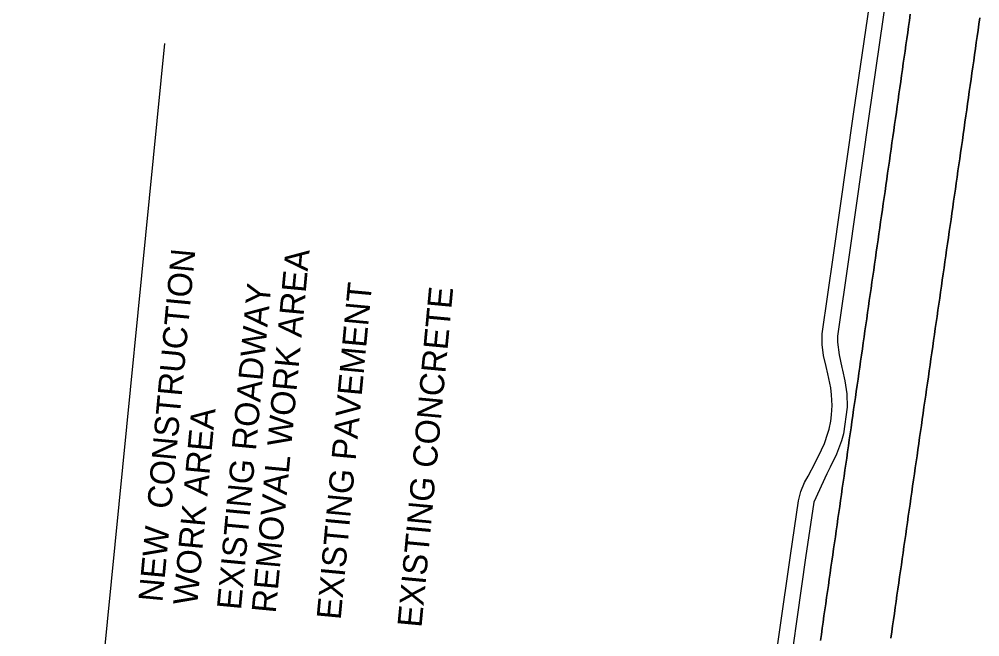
# Model space of a CAD drawing. Extents: x 1795987 to 1799700, y 243690 to 251545.
# Drawn here: x 1797261.4 to 1797570.9, y 247453.1 to 247652.1 of the extents above; entities that cross this region are included whole.
import ezdxf

# ---------------------------------------------------------------- set-up
doc = ezdxf.new("R2010")
doc.units = 0
for name, color, linetype in [('EP', 7, 'Continuous'), ('Level 31', 7, 'Continuous'), ('Prop_Horiz Alignment', 7, 'Continuous')]:
    doc.layers.add(name, color=color, linetype=linetype)

msp = doc.modelspace()

# ---------------------------------------------------------------- linework, layer by layer
at = {"layer": 'EP'}
for points in [[(1797502.98, 247431.42), (1797509.89, 247479.28), (1797512.41, 247496.92), (1797513.21, 247499.92), (1797514.39, 247502.79), (1797515.55, 247504.9), (1797517.77, 247509.13), (1797519.86, 247513.31), (1797520.78, 247515.42), (1797521.93, 247518.67), (1797522.28, 247519.96), (1797522.83, 247522.6), (1797523.1, 247524.61), (1797523.26, 247527.63), (1797523.1, 247531.02), (1797522.82, 247533.27), (1797521.91, 247537.81), (1797521.35, 247540.15), (1797520.54, 247543.7), (1797520.12, 247547.31), (1797520.09, 247550.71), (1797523.74, 247576.05), (1797530.2, 247621.54), (1797536.99, 247668.47)], [(1797541.84, 247667.67), (1797535.11, 247620.83), (1797528.62, 247575.39), (1797524.96, 247549.93), (1797525.06, 247548.02), (1797525.55, 247543.91), (1797526.45, 247539.86), (1797526.65, 247538.96), (1797527.41, 247535.59), (1797527.98, 247531.38), (1797528.16, 247527.13), (1797526.97, 247518.48), (1797526.28, 247516.25), (1797524.64, 247511.95), (1797522.63, 247507.8), (1797522.17, 247506.93), (1797521.53, 247505.59), (1797517.43, 247496.48), (1797514.72, 247478.52), (1797507.92, 247430.67)]]:
    msp.add_lwpolyline(points, dxfattribs=at)
at = {"layer": 'Level 31'}
msp.add_line((1797261.35, 247170.53), (1797308.29, 247644.28), dxfattribs=at)
at = {"layer": 'Prop_Horiz Alignment'}
for points in [[(1797519.54, 247451.89), (1797519.82, 247453.87), (1797520.1, 247455.84), (1797520.38, 247457.81), (1797520.66, 247459.79), (1797520.94, 247461.76), (1797521.23, 247463.73), (1797521.51, 247465.7), (1797521.79, 247467.68), (1797522.07, 247469.65), (1797522.35, 247471.62), (1797522.63, 247473.59), (1797522.91, 247475.55), (1797523.2, 247477.5), (1797523.48, 247479.45), (1797523.76, 247481.4), (1797524.04, 247483.36), (1797524.32, 247485.31), (1797524.6, 247487.26), (1797524.88, 247489.21), (1797525.16, 247491.17), (1797525.44, 247493.12), (1797525.72, 247495.07), (1797526, 247497.02), (1797526.28, 247498.98), (1797526.56, 247500.93), (1797526.85, 247502.88), (1797527.13, 247504.83), (1797527.41, 247506.79), (1797527.69, 247508.74), (1797527.97, 247510.69), (1797528.25, 247512.64), (1797528.53, 247514.6), (1797528.81, 247516.55), (1797529.09, 247518.5), (1797529.37, 247520.45), (1797529.65, 247522.41), (1797529.93, 247524.36), (1797530.21, 247526.31), (1797530.49, 247528.26), (1797530.78, 247530.22), (1797531.06, 247532.17), (1797531.34, 247534.12), (1797531.62, 247536.07), (1797531.9, 247538.03), (1797532.18, 247539.98), (1797532.46, 247541.93), (1797532.74, 247543.88), (1797533.02, 247545.84), (1797533.3, 247547.79), (1797533.58, 247549.74), (1797533.86, 247551.7), (1797534.14, 247553.65), (1797534.42, 247555.6), (1797534.71, 247557.55), (1797534.99, 247559.51), (1797535.27, 247561.46), (1797535.55, 247563.41), (1797535.83, 247565.36), (1797536.11, 247567.32), (1797536.39, 247569.27), (1797536.67, 247571.22), (1797536.95, 247573.17), (1797537.23, 247575.13), (1797537.51, 247577.08), (1797537.79, 247579.03), (1797538.07, 247580.98), (1797538.35, 247582.94), (1797538.64, 247584.89), (1797538.92, 247586.84), (1797539.2, 247588.79), (1797539.48, 247590.75), (1797539.76, 247592.7), (1797540.04, 247594.65), (1797540.32, 247596.6), (1797540.6, 247598.56), (1797540.88, 247600.51), (1797541.16, 247602.46), (1797541.44, 247604.41), (1797541.72, 247606.37), (1797542, 247608.32), (1797542.29, 247610.27), (1797542.57, 247612.24), (1797542.85, 247614.22), (1797543.13, 247616.19), (1797543.41, 247618.17), (1797543.69, 247620.14), (1797543.97, 247622.11), (1797544.25, 247624.09), (1797544.53, 247626.06), (1797544.81, 247628.04), (1797545.1, 247630.01), (1797545.38, 247631.98), (1797545.66, 247633.96), (1797545.94, 247635.93), (1797546.22, 247637.9), (1797546.5, 247639.88), (1797546.78, 247641.85), (1797547.06, 247643.83), (1797547.34, 247645.8), (1797547.63, 247647.77), (1797547.91, 247649.75), (1797548.19, 247651.72), (1797548.47, 247653.7)], [(1797548.47, 247653.7), (1797548.19, 247651.72), (1797547.91, 247649.75), (1797547.63, 247647.77), (1797547.34, 247645.8), (1797547.06, 247643.83), (1797546.78, 247641.85), (1797546.5, 247639.88), (1797546.22, 247637.9), (1797545.94, 247635.93), (1797545.66, 247633.96), (1797545.38, 247631.98), (1797545.1, 247630.01), (1797544.81, 247628.04), (1797544.53, 247626.06), (1797544.25, 247624.09), (1797543.97, 247622.11), (1797543.69, 247620.14), (1797543.41, 247618.17), (1797543.13, 247616.19), (1797542.85, 247614.22), (1797542.57, 247612.24), (1797542.29, 247610.27), (1797542, 247608.32), (1797541.72, 247606.37), (1797541.44, 247604.41), (1797541.16, 247602.46), (1797540.88, 247600.51), (1797540.6, 247598.56), (1797540.32, 247596.6), (1797540.04, 247594.65), (1797539.76, 247592.7), (1797539.48, 247590.75), (1797539.2, 247588.79), (1797538.92, 247586.84), (1797538.64, 247584.89), (1797538.35, 247582.94), (1797538.07, 247580.98), (1797537.79, 247579.03), (1797537.51, 247577.08), (1797537.23, 247575.13), (1797536.95, 247573.17), (1797536.67, 247571.22), (1797536.39, 247569.27), (1797536.11, 247567.32), (1797535.83, 247565.36), (1797535.55, 247563.41), (1797535.27, 247561.46), (1797534.99, 247559.51), (1797534.71, 247557.55), (1797534.42, 247555.6), (1797534.14, 247553.65), (1797533.86, 247551.7), (1797533.58, 247549.74), (1797533.3, 247547.79), (1797533.02, 247545.84), (1797532.74, 247543.88), (1797532.46, 247541.93), (1797532.18, 247539.98), (1797531.9, 247538.03), (1797531.62, 247536.07), (1797531.34, 247534.12), (1797531.06, 247532.17), (1797530.78, 247530.22), (1797530.49, 247528.26), (1797530.21, 247526.31), (1797529.93, 247524.36), (1797529.65, 247522.41), (1797529.37, 247520.45), (1797529.09, 247518.5), (1797528.81, 247516.55), (1797528.53, 247514.6), (1797528.25, 247512.64), (1797527.97, 247510.69), (1797527.69, 247508.74), (1797527.41, 247506.79), (1797527.13, 247504.83), (1797526.85, 247502.88), (1797526.56, 247500.93), (1797526.28, 247498.98), (1797526, 247497.02), (1797525.72, 247495.07), (1797525.44, 247493.12), (1797525.16, 247491.17), (1797524.88, 247489.21), (1797524.6, 247487.26), (1797524.32, 247485.31), (1797524.04, 247483.36), (1797523.76, 247481.4), (1797523.48, 247479.45), (1797523.2, 247477.5), (1797522.91, 247475.55), (1797522.63, 247473.59), (1797522.35, 247471.62), (1797522.07, 247469.65), (1797521.79, 247467.68), (1797521.51, 247465.7), (1797521.23, 247463.73), (1797520.94, 247461.76), (1797520.66, 247459.79), (1797520.38, 247457.81), (1797520.1, 247455.84), (1797519.82, 247453.87), (1797519.54, 247451.89)], [(1797570.86, 247652.5), (1797570.58, 247650.53), (1797570.3, 247648.55), (1797570.02, 247646.58), (1797569.74, 247644.61), (1797569.45, 247642.63), (1797569.17, 247640.66), (1797568.89, 247638.69), (1797568.61, 247636.71), (1797568.33, 247634.74), (1797568.05, 247632.77), (1797567.77, 247630.79), (1797567.49, 247628.82), (1797567.21, 247626.84), (1797566.92, 247624.87), (1797566.64, 247622.9), (1797566.36, 247620.92), (1797566.08, 247618.95), (1797565.8, 247616.98), (1797565.52, 247615), (1797565.24, 247613.03), (1797564.96, 247611.05), (1797564.68, 247609.08), (1797564.39, 247607.11), (1797564.11, 247605.15), (1797563.83, 247603.2), (1797563.55, 247601.25), (1797563.27, 247599.3), (1797562.99, 247597.34), (1797562.71, 247595.39), (1797562.43, 247593.44), (1797562.15, 247591.49), (1797561.87, 247589.53), (1797561.59, 247587.58), (1797561.31, 247585.63), (1797561.03, 247583.68), (1797560.75, 247581.72), (1797560.46, 247579.77), (1797560.18, 247577.82), (1797559.9, 247575.87), (1797559.62, 247573.91), (1797559.34, 247571.96), (1797559.06, 247570.01), (1797558.78, 247568.06), (1797558.5, 247566.1), (1797558.22, 247564.15), (1797557.94, 247562.2), (1797557.66, 247560.25), (1797557.38, 247558.29), (1797557.1, 247556.34), (1797556.81, 247554.39), (1797556.53, 247552.43), (1797556.25, 247550.48), (1797555.97, 247548.53), (1797555.69, 247546.58), (1797555.41, 247544.62), (1797555.13, 247542.67), (1797554.85, 247540.72), (1797554.57, 247538.77), (1797554.29, 247536.81), (1797554.01, 247534.86), (1797553.73, 247532.91), (1797553.45, 247530.96), (1797553.17, 247529), (1797552.88, 247527.05), (1797552.6, 247525.1), (1797552.32, 247523.15), (1797552.04, 247521.19), (1797551.76, 247519.24), (1797551.48, 247517.29), (1797551.2, 247515.34), (1797550.92, 247513.38), (1797550.64, 247511.43), (1797550.36, 247509.48), (1797550.08, 247507.53), (1797549.8, 247505.57), (1797549.52, 247503.62), (1797549.23, 247501.67), (1797548.95, 247499.72), (1797548.67, 247497.76), (1797548.39, 247495.81), (1797548.11, 247493.86), (1797547.83, 247491.91), (1797547.55, 247489.95), (1797547.27, 247488), (1797546.99, 247486.05), (1797546.71, 247484.09), (1797546.43, 247482.14), (1797546.15, 247480.19), (1797545.87, 247478.24), (1797545.59, 247476.28), (1797545.3, 247474.33), (1797545.02, 247472.38), (1797544.74, 247470.43), (1797544.46, 247468.45), (1797544.18, 247466.48), (1797543.9, 247464.51), (1797543.62, 247462.54), (1797543.34, 247460.56), (1797543.05, 247458.59), (1797542.77, 247456.62), (1797542.49, 247454.65), (1797542.21, 247452.67)], [(1797542.21, 247452.67), (1797542.49, 247454.65), (1797542.77, 247456.62), (1797543.05, 247458.59), (1797543.34, 247460.56), (1797543.62, 247462.54), (1797543.9, 247464.51), (1797544.18, 247466.48), (1797544.46, 247468.45), (1797544.74, 247470.43), (1797545.02, 247472.38), (1797545.3, 247474.33), (1797545.59, 247476.28), (1797545.87, 247478.24), (1797546.15, 247480.19), (1797546.43, 247482.14), (1797546.71, 247484.09), (1797546.99, 247486.05), (1797547.27, 247488), (1797547.55, 247489.95), (1797547.83, 247491.91), (1797548.11, 247493.86), (1797548.39, 247495.81), (1797548.67, 247497.76), (1797548.95, 247499.72), (1797549.23, 247501.67), (1797549.52, 247503.62), (1797549.8, 247505.57), (1797550.08, 247507.53), (1797550.36, 247509.48), (1797550.64, 247511.43), (1797550.92, 247513.38), (1797551.2, 247515.34), (1797551.48, 247517.29), (1797551.76, 247519.24), (1797552.04, 247521.19), (1797552.32, 247523.15), (1797552.6, 247525.1), (1797552.88, 247527.05), (1797553.17, 247529), (1797553.45, 247530.96), (1797553.73, 247532.91), (1797554.01, 247534.86), (1797554.29, 247536.81), (1797554.57, 247538.77), (1797554.85, 247540.72), (1797555.13, 247542.67), (1797555.41, 247544.62), (1797555.69, 247546.58), (1797555.97, 247548.53), (1797556.25, 247550.48), (1797556.53, 247552.43), (1797556.81, 247554.39), (1797557.1, 247556.34), (1797557.38, 247558.29), (1797557.66, 247560.25), (1797557.94, 247562.2), (1797558.22, 247564.15), (1797558.5, 247566.1), (1797558.78, 247568.06), (1797559.06, 247570.01), (1797559.34, 247571.96), (1797559.62, 247573.91), (1797559.9, 247575.87), (1797560.18, 247577.82), (1797560.46, 247579.77), (1797560.75, 247581.72), (1797561.03, 247583.68), (1797561.31, 247585.63), (1797561.59, 247587.58), (1797561.87, 247589.53), (1797562.15, 247591.49), (1797562.43, 247593.44), (1797562.71, 247595.39), (1797562.99, 247597.34), (1797563.27, 247599.3), (1797563.55, 247601.25), (1797563.83, 247603.2), (1797564.11, 247605.15), (1797564.39, 247607.11), (1797564.68, 247609.08), (1797564.96, 247611.05), (1797565.24, 247613.03), (1797565.52, 247615), (1797565.8, 247616.98), (1797566.08, 247618.95), (1797566.36, 247620.92), (1797566.64, 247622.9), (1797566.92, 247624.87), (1797567.21, 247626.84), (1797567.49, 247628.82), (1797567.77, 247630.79), (1797568.05, 247632.77), (1797568.33, 247634.74), (1797568.61, 247636.71), (1797568.89, 247638.69), (1797569.17, 247640.66), (1797569.45, 247642.63), (1797569.74, 247644.61), (1797570.02, 247646.58), (1797570.3, 247648.55), (1797570.58, 247650.53), (1797570.86, 247652.5)]]:
    msp.add_lwpolyline(points, dxfattribs=at)

# ---------------------------------------------------------------- texts
at = {"layer": 'Level 31'}
for s, height, p in [('NEW  CONSTRUCTION', 7.7999, (1797307.5, 247464.07)), ('REMOVAL WORK AREA', 7.7999, (1797343.98, 247460.51)), ('EXISTING ROADWAY', 7.7999, (1797332.79, 247461.56)), ('EXISTING PAVEMENT', 7.7999, (1797364.92, 247458.39)), ('EXISTING CONCRETE', 7.7999, (1797390.96, 247455.89)), ('WORK AREA', 7.8, (1797318.69, 247463.02))]:
    msp.add_text(s, height=height, rotation=84.6544, dxfattribs=at).set_placement(p)

doc.saveas('drawing.dxf')
